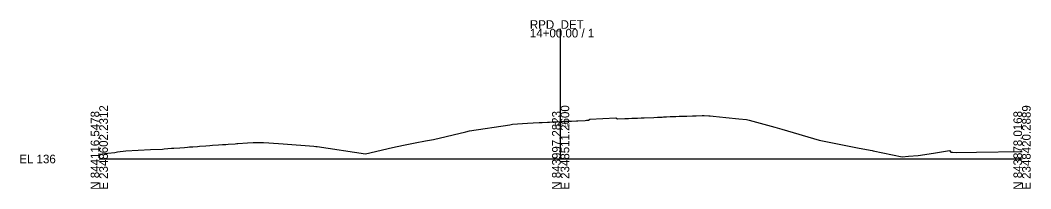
# Model space of a CAD drawing. Extents: x -26 to 2348503, y -10 to 844218.
# Drawn here: x -25.7 to 302.8, y 3990.3 to 4045.1 of the extents above; entities that cross this region are included whole.
import ezdxf

# ---------------------------------------------------------------- set-up
doc = ezdxf.new("R2010")
doc.units = 0
for name, color, linetype in [('Default', 7, 'Continuous'), ('Exist Cross Section Cell', 7, 'Continuous'), ('Exist XS Center Line Elevation Label', 7, 'Continuous'), ('Exist XS Ground Line', 7, 'Continuous')]:
    doc.layers.add(name, color=color, linetype=linetype)

msp = doc.modelspace()

# ---------------------------------------------------------------- linework, layer by layer
at = {"layer": 'Exist Cross Section Cell'}
for p, q in [((150, 4000), (150, 4042.34)), ((0, 4000), (150, 4000)), ((150, 4000), (300, 4000))]:
    msp.add_line(p, q, dxfattribs=at)
at = {"layer": 'Exist XS Ground Line'}
msp.add_lwpolyline([(0, 4001.61), (2.84, 4001.93), (5.03, 4002.16), (5.94, 4002.28), (8.64, 4002.69), (16.7, 4003.05), (20.57, 4003.25), (21.14, 4003.3), (23.48, 4003.48), (24.2, 4003.55), (26.2, 4003.67), (27.69, 4003.78), (28.64, 4003.85), (29.36, 4003.91), (30.47, 4003.99), (31.89, 4004.09), (32.54, 4004.14), (34.7, 4004.29), (35.92, 4004.4), (36.78, 4004.46), (38.76, 4004.58), (40.07, 4004.68), (41.11, 4004.76), (41.92, 4004.81), (44.17, 4004.97), (44.68, 4005), (45.07, 4005.03), (48.21, 4005.23), (50.08, 4005.35), (51.43, 4005.34), (52.06, 4005.34), (53.02, 4005.33), (53.38, 4005.33), (55.18, 4005.24), (59.78, 4004.98), (69.76, 4004.14), (70.39, 4004.08), (70.83, 4004.02), (86.6, 4001.65), (95.31, 4003.73), (98.93, 4004.55), (102.66, 4005.29), (106.07, 4005.94), (108.67, 4006.37), (119.15, 4008.81), (120.34, 4009.11), (133.48, 4011.12), (134.4, 4011.3), (139.22, 4011.69), (141.08, 4011.78), (143.07, 4011.87), (144.03, 4011.9), (145.7, 4011.96), (146.39, 4011.99), (147.32, 4012.04), (148.2, 4012.08), (148.86, 4012.12), (150, 4012.18), (151.43, 4012.25), (152, 4012.28), (153.55, 4012.34), (155.19, 4012.42), (155.56, 4012.44), (157.99, 4012.56), (158.41, 4012.58), (159.08, 4012.63), (159.49, 4012.95), (167.98, 4013.35), (168.53, 4013.04), (170.86, 4013.13), (171.36, 4013.15), (172.04, 4013.18), (173.18, 4013.24), (174.03, 4013.28), (174.95, 4013.32), (176.21, 4013.38), (176.76, 4013.41), (177.17, 4013.43), (180.31, 4013.55), (181.49, 4013.6), (182.96, 4013.65), (183.42, 4013.67), (183.84, 4013.69), (184.4, 4013.71), (185.64, 4013.77), (186.58, 4013.81), (187.43, 4013.84), (188.54, 4013.88), (189.21, 4013.91), (189.73, 4013.93), (191, 4013.97), (192.88, 4014.04), (193.19, 4014.05), (194.09, 4014.09), (195.98, 4014.11), (196.29, 4014.11), (196.7, 4014.1), (198.12, 4014.07), (198.6, 4014.06), (199.6, 4013.96), (203.73, 4013.55), (207.95, 4013.02), (210.43, 4012.86), (211.24, 4012.64), (219.65, 4010.37), (221.86, 4009.68), (234.03, 4006.14), (234.57, 4005.99), (241.63, 4004.59), (247.02, 4003.55), (251.22, 4002.71), (251.55, 4002.64), (261.02, 4000.71), (263.04, 4000.89), (266.25, 4001.18), (271.22, 4001.93), (276.4, 4002.74), (276.82, 4002.24), (277.42, 4002.19), (278.68, 4002.15), (285.15, 4002.26), (299.41, 4002.4), (300, 4002.39)], dxfattribs=at)

# ---------------------------------------------------------------- texts
at = {"layer": 'Default'}
msp.add_text('-', height=0.0001, dxfattribs=at).set_placement((0, 4000))
at = {"layer": 'Exist Cross Section Cell'}
for s, p in [('RPD_DET', (140, 4042.34)), ('14+00.00 / 1', (140, 4039.54)), ('EL 136', (-26, 3998.6))]:
    msp.add_text(s, height=2.8, dxfattribs=at).set_placement(p)
for s, p in [('N 844116.5478', (0, 3990)), ('E 2348602.2312', (2.8, 3990)), ('N 843997.2823', (150, 3990)), ('E 2348511.2600', (152.8, 3990)), ('N 843878.0168', (300, 3990)), ('E 2348420.2889', (302.8, 3990))]:
    msp.add_text(s, height=2.8, rotation=90, dxfattribs=at).set_placement(p)
at = {"layer": 'Exist XS Center Line Elevation Label'}
msp.add_text('148.18', height=1.2, dxfattribs=at).set_placement((147.89, 4010.58))

doc.saveas('drawing.dxf')
